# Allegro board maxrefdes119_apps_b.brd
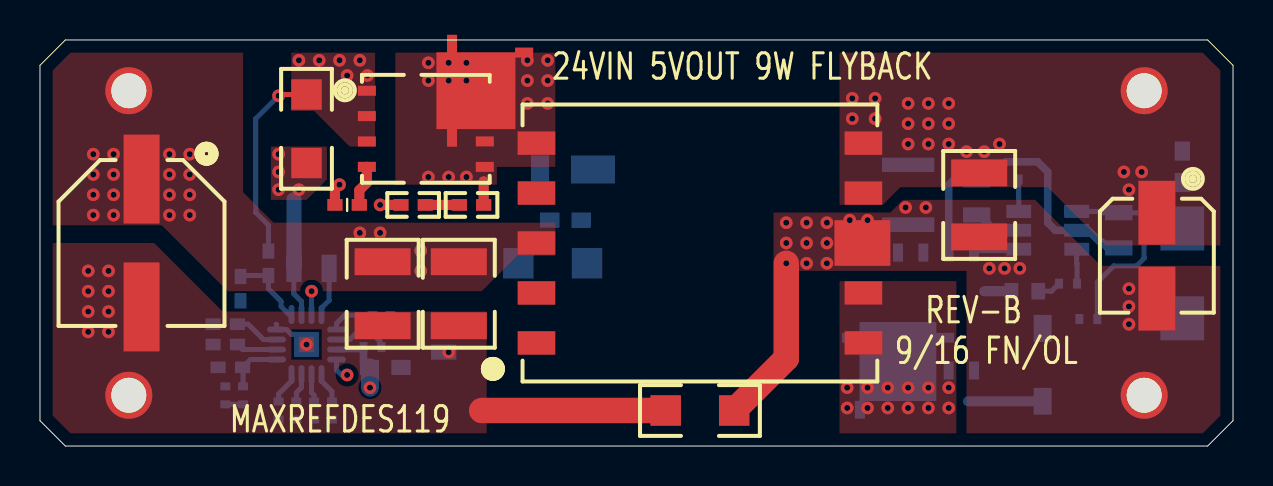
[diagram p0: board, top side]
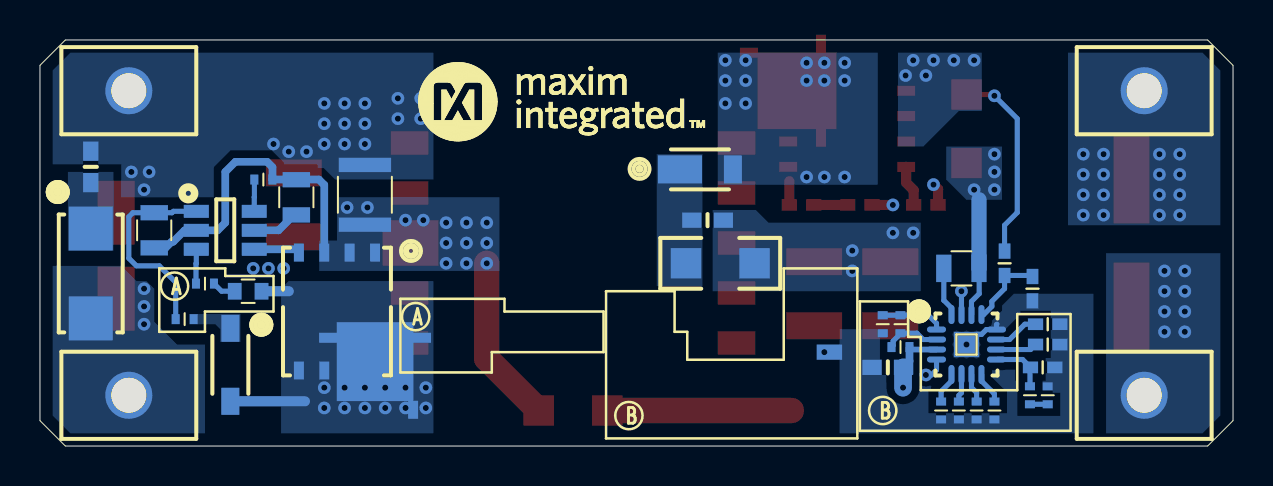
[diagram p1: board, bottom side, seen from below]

Outline 59.69 x 20.32 mm; copper layers: TOP, LAYER2, LAYER3, BOTTOM. Coordinates in mm from the lower left corner of the outline.
Outline path: 0,19.05 1.27,20.32 58.42,20.32 59.69,19.05 59.69,1.27 58.42,0 1.27,0 0,1.27 0,19.05

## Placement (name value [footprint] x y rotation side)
C1  47UF  [CAPAE830X690M]  5.08 10.16 270 top
C2  10UF  [1210]  20.95 7.62 270 top
C3  10UF  [1210]  17.14 7.62 270 top
C6  1UF  [0603#2]  17.27 3.94 0 bottom
C7  2.2UF  [CAPC2012X140M]  13.59 8.89 0 bottom
C8  22000PF  [0603#2]  26.29 11.3 0 bottom
C9  4700PF  [0402]  9.27 5.08 180 bottom
C10  0.033UF  [0402#2]  9.27 2.54 90 bottom
C12  330PF  [0402]  9.53 3.94 180 bottom
C14  1000PF  [1206]  33.02 1.78 0 top
C15  2.2UF  [CAPC2012X140M]  53.98 10.79 270 bottom
C16  2.2UF  [CAPC2012X140M]  46.86 12.45 90 bottom
C17  100UF  [1210]  46.99 12.06 270 top
C18  220UF  [CAPAE530X600M]  55.88 9.53 270 top
C19  OPEN  [0402]  10.03 7.87 270 bottom
C20  OPEN  [1210#2]  43.43 12.57 270 bottom
D1  DFLS2100  [POWERI123]  26.67 13.84 180 bottom
D2  1N4148W-7-F  [SOD3718X135M]  50.16 4.06 270 bottom
D3  5.6V  [DIOM5528X230M]  57.15 8.64 270 bottom
EV_KIT_BOX1  SMALL BOX  [EVKIT_PACKAGING]  91.82 82.42 0 top
GNDO  FWJ-01-01-T-S  [SAMTEC_FWJ-01-01-X-X]  55.24 2.54 90 bottom
NOREF  -  []  0 19.05 0 top
NOREF#2  -  []  31.75 52.7 0 top
NOREF#3  -  []  55.24 2.54 90 top
NOREF#4  -  []  4.45 17.78 0 top
NOREF#5  -  []  59 0.58 0 top
NOREF#6  -  []  1.27 0 90 top
NOREF#7  -  []  12.7 -8.26 0 top
NOREF#8  -  []  38.73 17.14 180 bottom
PGND  FWJ-01-01-T-S  [SAMTEC_FWJ-01-01-X-X]  4.45 2.54 90 bottom
PTC1  470  [0603]  49.28 7.75 0 bottom
Q1  FDMS86200DC  [SON127P615X500X112-8M_POWERPAK_SINGLE]  19.3 15.88 0 top
Q2  SIR426DP-T1-GE3  [SON127P615X500X112-8M_POWERPAK_SINGLE]  44.83 6.73 270 bottom
R1  10K  [0402#2]  17.53 6.1 90 bottom
R2  280K  [0402#2]  16.64 4.95 180 bottom
R3  11.8K  [0402#2]  16.64 6.1 270 bottom
R4  0  [0402]  21.59 12.06 180 top
R5  232K  [0402]  18.67 12.06 180 top
R6  10K  [0402#2]  14.61 1.78 270 bottom
R7  OPEN  [0402#2]  13.72 1.78 270 bottom
R8  75K  [0402#2]  12.83 1.78 270 bottom
R9  11.5K  [1206]  25.65 9.14 0 bottom
R10  140K  [0402#2]  11.94 1.78 270 bottom
R11  54.9K  [0402]  9.27 6.1 180 bottom
R12  9.09K  [0402#2]  10.16 2.54 270 bottom
R13  2.2  [0402]  15.37 12.06 0 top
R16  0.03  [1206]  13.34 15.88 270 top
R17  10  [0402#2]  52.45 6.35 180 bottom
R18  2.43K  [0402#2]  51.44 8.13 180 bottom
R19  100K  [0402#2]  48.51 13.34 180 bottom
R21  49.9  [0603#2]  57.15 13.97 270 bottom
R23  0  [0402]  11.43 9.14 90 bottom
T1  750316204  [XFMR_750316204]  33.02 10.16 0 top
U1  MAX17690ATE+  [QFN50P300X300X80-17M]  13.34 5.08 180 bottom
U2  MAX17606AZT+  [SOT95P280X110-6M]  50.42 10.79 180 bottom
VIN  FWJ-01-01-T-S  [SAMTEC_FWJ-01-01-X-X]  4.45 17.78 90 bottom
VOUT  FWJ-01-01-T-S  [SAMTEC_FWJ-01-01-X-X]  55.24 17.78 90 bottom
W1  -  [EVKIT_WIRE]  7.62 22.23 0 top

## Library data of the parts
C1 = CAP_POL: part number: CAP_POL_CASEE-CAPAE830X690M,47UF,20-0047U-A49
C2 C3 = CAP_NP: alternate symbols: CAPC3225X270L; part number: CAP_NP_1210CAP-1210,10UF,20-0010U-B40
C6 = CAP_NP: alternate symbols: (0603_NOSILK); part number: CAP_NP_0603CAP-0603,1UF,20-0001U-14
C7 C15 C16 = CAP_NP: alternate symbols: CAPC2012X145L; part number: CAP_NP_0805CAP-CAPC2012X140M,2.2UF,20-002U2-CA42
C8 = CAP_NP: alternate symbols: 0603_NOSILK,CAPC1608X90L; part number: CAP_NP_0603CAP-0603,22000PF,20-0U022-08
C9 = CAP_NP: alternate symbols: 0402_NOSILK,CAPC1005X50L; part number: CAP_NP_0402CAP-0402,4700PF,20-4700P-14
C10 = CAP_NP: alternate symbols: 0402_NOSILK,CAPC1005X50L; part number: CAP_NP_0402CAP-0402,0.033UF,20-0U033-04C
C12 = CAP_NP: alternate symbols: 0402_NOSILK,CAPC1005X50L; part number: CAP_NP_0402CAP-0402,330PF,20-0330P-F3
C14 = CAP_NP: part number: CAP_NP_1206CAP-1206,1000PF,20-1000P-08B
C17 = CAP_NP: alternate symbols: CAPC3225X270L; part number: CAP_NP_1210CAP-1210,100UF,20-0100U-CA19
C18 = CAP_POL: part number: CAP_POL_CASE_B6-CAPAE530X600M,220UF,20-0220U-CA36
C19 = EVK_GENERIC_CAPACITORS: alternate symbols: 0402_NOSILK,CAPC1005X50L; part number: EVK_GENERIC_CAPACITORS_0402CAP-0402,N/A
C20 = EVK_GENERIC_CAPACITORS: alternate symbols: CAPC3225X270L; part number: EVK_GENERIC_CAPACITORS_1210CAP-1210,N/A
D1 = DIO_SCHOTTKY: alternate symbols: SODFL3717X100L; part number: DIO_SCHOTTKY_POWERI123-POWERI123,DFLS2100,30-DFLS2100-00
D2 = DIO_SWITCH: part number: DIO_SWITCH_SOD-123-SOD3718X135M,1N4148W-7-F,30-1N4148W7F-00
D3 = DIO_ZENER: part number: DIO_ZENER_DO-214AC-DIOM5528X230M,5.6V,30-SMAZ5V6-00
EV_KIT_BOX1 = EV_KIT_BOX: part number: EV_KIT_BOX_ACCESSORY-N/A,SMALL BOX,EVKIT_PACKAGING
GNDO PGND VIN VOUT = HEADER_1P: part number: HEADER_1P_TH-SAMTEC_FWJ-01-01-X-X,FWJ-01-01-T-S,01-FWJ0101TS1P-19
PTC1 = THERMISTOR_SMD: alternate symbols: RESC1608X90L; part number: THERMISTOR_SMD_0603-0603,470,83-0470R-0AD
Q1 = TRAN_NCH_8P: alternate symbols: SON127P615X500X112-8L_POWERPAK_SINGLE; part number: TRAN_NCH_8P_POWERPAK-SINGLE-SON127P615X500X112-8M_POWERPAK_SINGLE,FDMS86200DC,90-FDMS86200DC-23
Q2 = TRAN_NCH_8P: part number: TRAN_NCH_8P_POWERPAK-SINGLE-SON127P615X500X112-8M_POWERPAK_SINGLE,SIR426DP-T1-GE3,90-SIR426DPT1GE3-23
R1 R6 = RES: alternate symbols: 0402_NOSILK,RESC1005X50L; part number: RES_0402RES-0402,10K,80-0010K-23E
R2 = RES: alternate symbols: 0402_NOSILK,RESC1005X50L; part number: RES_0402RES-0402,280K,80-0280K-BA37
R3 = RES: alternate symbols: 0402_NOSILK,RESC1005X50L; part number: RES_0402RES-0402,11.8K,80-011K8-AA23
R4 R23 = RES: alternate symbols: 0402_NOSILK,RESC1005X50L; part number: RES_0402RES-0402,0,80-0000R-BA38
R5 = RES: alternate symbols: 0402_NOSILK,RESC1005X50L; part number: RES_0402RES-0402,232K,80-0232K-BA37
R7 = EVK_GENERIC_RESISTORS: alternate symbols: 0402_NOSILK,RESC1005X50L; part number: EVK_GENERIC_RESISTORS_0402RES-0402,N/A
R8 = RES: alternate symbols: 0402_NOSILK,RESC1005X50L; part number: RES_0402RES-0402,75K,80-0075K-BA29
R9 = RES: part number: RES_1206RES-1206,11.5K,80-011K5-69
R10 = RES: alternate symbols: (0402_NOSILK,RESC1005X50L); part number: RES_0402RES-0402,140K,80-0140K-18
R11 = RES: alternate symbols: 0402_NOSILK,RESC1005X50L; part number: RES_0402RES-0402,54.9K,80-054K9-BA37
R12 = RES: alternate symbols: 0402_NOSILK,RESC1005X50L; part number: RES_0402RES-0402,9.09K,80-09K09-AA23
R13 = RES: alternate symbols: 0402_NOSILK,RESC1005X50L; part number: RES_0402RES-0402,2.2,80-002R2-BA36
R16 = RES: alternate symbols: RESC3116X60L; part number: RES_1206RES-1206,0.03,80-00R03-BA25
R17 = RES: alternate symbols: 0402_NOSILK,RESC1005X50L; part number: RES_0402RES-0402,10,80-0010R-BA36
R18 = RES: alternate symbols: (0402_NOSILK,RESC1005X50L); part number: RES_0402RES-0402,2.43K,80-02K43-18
R19 = RES: alternate symbols: 0402_NOSILK,RESC1005X50L; part number: RES_0402RES-0402,100K,80-0100K-BA37
R21 = RES: alternate symbols: 0603_NOSILK,RESC1608X90L; part number: RES_0603RES-0603,49.9,80-049R9-BA59
T1 = 750316204: part number: 750316204_SMD10-XFMR_750316204,750316204,12-750316204-01
U1 = MAX17690: part number: MAX17690_TQFN16-EP-QFN50P300X300X80-17M,MAX17690ATE+,10-MAX17690ATE-T
U2 = MAX17606: part number: MAX17606_SOT23-6-SOT95P280X110-6M,MAX17606AZT+,10-MAX17606AZT-Z
W1 = EVKIT_WIRE: part number: EVKIT_WIRE_WIRE-EVKIT_WIRE,N/A,EVKIT_WIRE

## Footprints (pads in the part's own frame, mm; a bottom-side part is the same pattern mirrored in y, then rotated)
0402
  rect 0.762x0.584 smd: 1(-0.61,0) 2(0.61,0)
0402#2
  rect 0.4x0.5 smd: 1(-0.45,0) 2(0.45,0)
0603
  rect 0.69x0.83 smd: 1(-0.67,0) 2(0.67,0)
0603#2
  rect 0.965x0.762 smd: 1(-0.787,0) 2(0.787,0)
1206
  rect 1.524x1.524 smd: 1(-1.714,0) 2(1.714,0)
1210
  rect 1.35x2.8 smd: 1(-1.6,0) 2(1.6,0)
1210#2
  rect 0.72x2.62 smd: 1(-1.495,0) 2(1.495,0)
CAPAE530X600M
  rect 3.2x1.85 smd: A(-2.15,0) K(2.15,0)
CAPAE830X690M
  rect 4.45x1.8 smd: 1(-3.2,0) 2(3.2,0)
CAPC2012X140M
  rect 0.76x1.37 smd: 1(-0.88,0) 2(0.88,0)
DIOM5528X230M
  rect 2.2x2.2 smd: A(2.25,0) C(-2.25,0)
POWERI123
  rect 0.9x1.4 smd: A(1.65,0)
  rect 2.2x1.4 smd: C(-0.999,0)
QFN50P300X300X80-17M
  oval 0.95x0.3 smd: 1(-1.5,0.75) 2(-1.5,0.25) 3(-1.5,-0.25) 4(-1.5,-0.75) 9(1.5,-0.75) 10(1.5,-0.25) 11(1.5,0.25) 12(1.5,0.75)
  oval 0.3x0.95 smd: 5(-0.75,-1.5) 6(-0.25,-1.5) 7(0.25,-1.5) 8(0.75,-1.5) 13(0.75,1.5) 14(0.25,1.5) 15(-0.25,1.5) 16(-0.75,1.5)
  rect 1.25x1.25 smd: 17(0,0)
SAMTEC_FWJ-01-01-X-X
  round 2.35 hole 1.75: 1(0,0)
SOD3718X135M
  rect 1.35x0.9 smd: A(1.825,0) C(-1.825,0)
SON127P615X500X112-8M_POWERPAK_SINGLE
  rect 0.9x0.5 smd: 1(-2.95,1.905) 2(-2.95,0.635) 3(-2.95,-0.635) 4(-2.95,-1.905) 5(2.95,-1.905) 6(2.95,-0.635) 7(2.95,0.635)
  custom 1.209x1.209 smd: 8(2.95,1.905)
SOT95P280X110-6M
  rect 1.25x0.65 smd: 1(-1.45,0.95) 2(-1.45,0) 3(-1.45,-0.95) 4(1.45,-0.95) 5(1.45,0) 6(1.45,0.95)
XFMR_750316204
  rect 1.88x1.17 smd: 1(-8.18,-5) 2(-8.18,-2.5) 3(-8.18,0) 4(-8.18,2.5) 5(-8.18,5) 6(8.18,5) 7(8.18,2.5) 8(8.18,0) 9(8.18,-2.5) 10(8.18,-5)

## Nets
GNDO: C14.2 C15.2 C16.2 C17.2 C18.K(B) C20.2 D3.A GNDO.1 Q2.1(S1) Q2.2(S2) Q2.3(S3) R19.2 U2.2(GND)
PGND: C1.2(B) C2.2 C3.2 C7.1 C14.1 PGND.1 R16.2 U1.14(PGND)
SGND: C6.2 C9.2 C10.2 C12.2 C19.2 R1.1 R6.2 R7.2 R8.2 R10.2 R11.2 U1.12(SGND) U1.17(EP)
VIN: C1.1(A) C2.1 C3.1 C6.1 C8.1 R2.2 R9.1 T1.3 U1.3(VIN) VIN.1
LX: D1.A Q1.5(D1) Q1.6(D2) Q1.7(D3) Q1.8(D4) R4.1 T1.5
UNNAMED_4_CAPNP_I112_2: C8.2 D1.C(K) R9.2
UNNAMED_4_CAPNP_I179_2: C7.2 U1.16(INTVCC)
UNNAMED_4_CAPNP_I180_1: C16.1 U2.5(VDRV)
UNNAMED_4_CAPNP_I182_1: C12.1 R12.1 U1.9(COMP)
UNNAMED_4_CAPNP_I183_1: C10.1 R12.2
UNNAMED_4_CAPNP_I184_1: C15.1 R17.1 U2.1(VIN)
UNNAMED_4_CAPNP_I219_1: C9.1 U1.10(SS)
UNNAMED_4_DIOSWITCH_I187_A: D2.A PTC1.1 Q2.5(D1) Q2.6(D2) Q2.7(D3) Q2.8(D4) T1.9 T1.10
UNNAMED_4_DIOSWITCH_I187_K: D2.C(K) R17.2
UNNAMED_4_DIOZENER_I178_K: D3.C(K) R21.2
UNNAMED_4_EVKGENERICRESISTORS_I167_1: R7.1 U1.6(TC)
UNNAMED_4_MAX17606_I176_DRN: R18.1 U2.3(DRN)
UNNAMED_4_MAX17606_I176_GATE: Q2.4(G) U2.4(GATE)
UNNAMED_4_MAX17606_I176_TOFF: R19.1 U2.6(TOFF)
UNNAMED_4_MAX17690_I155_CS: C19.1 R23.1 U1.13(CS)
UNNAMED_4_MAX17690_I155_EN: R2.1 R3.2 U1.2(EN/UVLO)
UNNAMED_4_MAX17690_I155_FB: R5.2 U1.4(FB)
UNNAMED_4_MAX17690_I155_NDRV: R13.1 U1.15(NDRV)
UNNAMED_4_MAX17690_I155_OVI: R1.2 R3.1 U1.1(OVI)
UNNAMED_4_MAX17690_I155_RIN: R10.1 U1.8(RIN)
UNNAMED_4_MAX17690_I155_RT: R11.1 U1.11(RT)
UNNAMED_4_MAX17690_I155_SET: R6.1 U1.5(SET)
UNNAMED_4_MAX17690_I155_VCM: R8.1 U1.7(VCM)
UNNAMED_4_RESSMD_I169_1: Q1.1(S1) Q1.2(S2) Q1.3(S3) R16.1 R23.2
UNNAMED_4_RESSMD_I171_1: R4.2 R5.1
UNNAMED_4_RESSMD_I173_2: PTC1.2 R18.2
UNNAMED_4_RESSMD_I175_2: Q1.4(G) R13.2
VOUT: C17.1 C18.A C20.1 R21.1 T1.6 T1.7 VOUT.1

Pads without a net: T1 1 2 4 8

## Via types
v1: diameter 0.635, hole 0.305, TOP to BOTTOM, 111 vias

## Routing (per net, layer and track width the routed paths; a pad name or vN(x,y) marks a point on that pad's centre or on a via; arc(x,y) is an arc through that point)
GNDO: length 24.2
  TOP w1.27: C14.2 37.34,4.38 v1(37.34,9.14)
  BOTTOM w0.381: 45.47,9.94 45.47,13.07 45.74,13.34 46.85,13.34 C16.2 46.87,13.34 R19.2 48.06,13.34 48.06,13.95 48.33,14.22 49.91,14.22 50.42,13.72 50.42,11.18 50.8,10.79 U2.2 52.45,10.79 53.02,10.23 53.1,10.23 53.41,9.91 C15.2
  vias: v1(37.34,11.18) v1(37.34,10.16) v1(38.35,11.18) v1(38.35,10.16) v1(38.35,9.14) v1(39.37,11.18) v1(39.37,10.16) v1(39.37,9.14) v1(40.51,11.3) v1(41.4,11.3) v1(43.31,11.94) v1(44.32,11.94) v1(47.5,8.89) v1(48.26,8.89) v1(49.02,8.89) v1(54.48,7.87) v1(54.48,6.99) v1(54.48,6.1)
PGND: length 15.3
  TOP w0.381: 22.1,1.78 21.97,1.65
  TOP w1.27: C14.1 22.1,1.78
  BOTTOM w0.254: C7.1 12.7,8.88 12.7,7.62 13.08,7.24 U1.14
  BOTTOM w0.762: C7.1 12.71,12.32
  vias: v1(2.41,8.76) v1(2.41,7.75) v1(2.41,6.73) v1(2.41,5.71) v1(3.43,8.76) v1(3.43,7.75) v1(3.43,6.73) v1(3.43,5.71) v1(11.94,14.61) v1(11.94,13.72) v1(11.94,12.83) v1(12.95,12.83) v1(20.45,4.7)
SGND: length 2.2
  BOTTOM w0.254: 13.21,5.08 v1(13.34,5.08) 12.83,5.59 12.58,5.59 12.34,5.83 U1.12 11.84,6.07 11.81,6.1
VIN: length 10.5
  LAYER3 w0.762: v1(19.05,8.76) 16.51,6.22 v1(16.51,2.92)
  BOTTOM w0.279: U1.3 16.06,4.83 R2.2
  BOTTOM w0.381: C6.1 16.19,4.23 R2.2
  BOTTOM w0.889: C6.1 16.51,3.91 v1(16.51,2.92)
  vias: v1(2.67,14.61) v1(2.67,13.59) v1(2.67,12.57) v1(2.67,11.56) v1(3.68,14.61) v1(3.68,13.59) v1(3.68,12.57) v1(3.68,11.56) v1(6.48,14.61) v1(6.48,13.59) v1(6.48,12.57) v1(6.48,11.56) v1(7.49,14.61) v1(7.49,13.59) v1(7.49,12.57) v1(7.49,11.56) v1(16,10.67) v1(17.02,10.67) v1(19.05,9.78)
LX: length 1.2
  TOP w0.508: R4.1 22.2,13.25
  vias: v1(19.43,19.18) v1(19.43,18.29) v1(19.43,13.46) v1(20.45,19.18) v1(20.45,18.29) v1(20.45,13.46) v1(21.34,19.18) v1(21.34,18.29) v1(21.34,13.46) v1(24.38,19.3) v1(24.38,18.29) v1(24.38,17.14) v1(25.4,19.3) v1(25.4,18.29) v1(25.4,17.14)
UNNAMED_4_CAPNP_I179_2: length 2.5
  BOTTOM w0.254: U1.16 14.09,6.9 14.47,7.29 C7.2
UNNAMED_4_CAPNP_I180_1: length 2.4
  BOTTOM w0.381: U2.5 47.75,10.79 46.98,11.57 C16.1
UNNAMED_4_CAPNP_I182_1: length 2.8
  BOTTOM w0.254: R12.1 10.16,3.91 C12.1 10.53,4.33 U1.9
UNNAMED_4_CAPNP_I183_1: length 0.9
  BOTTOM w0.254: R12.2 C10.1
UNNAMED_4_CAPNP_I184_1: length 10.3
  BOTTOM w0.254: R17.1 52.9,8.2 53.72,9.02 54.86,9.02 55.24,9.4 55.24,11.47 55.04,11.68 C15.1 53.09,11.68 53.02,11.75 U2.1
UNNAMED_4_CAPNP_I219_1: length 2.1
  BOTTOM w0.254: C9.1 10.13,4.83 U1.10
UNNAMED_4_DIOSWITCH_I187_A: length 5.1
  BOTTOM w0.508: D2.A 46.44,2.24 ; PTC1.1 47.24,7.75
  vias: v1(40.39,2.92) v1(40.39,1.91) v1(41.4,2.92) v1(41.4,1.91) v1(42.42,2.92) v1(42.42,1.91) v1(43.43,2.92) v1(43.43,1.91) v1(44.45,2.92) v1(44.45,1.91) v1(45.47,2.92) v1(45.47,1.91)
UNNAMED_4_EVKGENERICRESISTORS_I167_1: length 1.4
  BOTTOM w0.254: R7.1 13.72,2.54 13.59,2.67 U1.6
UNNAMED_4_MAX17606_I176_DRN: length 1.7
  BOTTOM w0.254: R18.1 51.89,9.12 51.87,9.14 U2.3
UNNAMED_4_MAX17606_I176_GATE: length 2.3
  BOTTOM w0.381: U2.4 46.9,9.84 Q2.4
UNNAMED_4_MAX17606_I176_TOFF: length 1.6
  BOTTOM w0.254: R19.1 48.96,12.46 48.97,12.45 U2.6
UNNAMED_4_MAX17690_I155_CS: length 3.9
  BOTTOM w0.254: U1.13 12.47,6.58 12.06,6.99 12.06,7.24 11.43,7.87 R23.1 10.08,8.53 C19.1
UNNAMED_4_MAX17690_I155_EN: length 2.8
  BOTTOM w0.254: R2.1 17,5.04 17,5.26 16.64,5.62 R3.2 15.82,5.65 15.5,5.33 U1.2
UNNAMED_4_MAX17690_I155_FB: length 12.5
  TOP w0.508: R5.2 v1(17.02,12.06)
  LAYER3 w0.508: v1(17.02,12.06) 15.75,12.06 14.99,11.3 14.99,7.24 15.37,6.86 v1(15.37,3.56)
  BOTTOM w0.254: v1(15.37,3.56) 15.09,3.56 14.83,3.81 U1.4
UNNAMED_4_MAX17690_I155_NDRV: length 8.2
  TOP w0.508: v1(14.99,13.08) 14.76,12.85 R13.1
  LAYER3 w0.508: v1(13.59,7.75) 13.59,11.68 v1(14.99,13.08)
  BOTTOM w0.254: U1.15 13.59,7.74 v1(13.59,7.75)
UNNAMED_4_MAX17690_I155_OVI: length 3.2
  BOTTOM w0.254: R1.2 R3.1 15.24,6.55 14.83,6.14 U1.1
UNNAMED_4_MAX17690_I155_RIN: length 1.6
  BOTTOM w0.254: R10.1 11.94,2.61 12.58,3.26 U1.8
UNNAMED_4_MAX17690_I155_RT: length 2.3
  BOTTOM w0.254: R11.1 10.41,6.1 11.18,5.33 U1.11
UNNAMED_4_MAX17690_I155_SET: length 1.6
  BOTTOM w0.254: R6.1 14.61,2.74 14.09,3.26 U1.5
UNNAMED_4_MAX17690_I155_VCM: length 1.5
  BOTTOM w0.254: R8.1 12.83,2.67 13.08,2.93 U1.7
UNNAMED_4_RESSMD_I169_1: length 9.9
  TOP w0.254: R16.1 12,17.59 v1(11.94,17.53)
  BOTTOM w0.254: R23.2 11.43,11.05 10.79,11.68 10.79,16.38 v1(11.94,17.53)
  vias: v1(12.95,19.3) v1(13.97,19.3) v1(14.99,19.3) v1(15.37,18.54) v1(16,19.3) v1(16.38,18.54)
UNNAMED_4_RESSMD_I171_1: length 1.7
  TOP w0.508: R4.2 R5.1
UNNAMED_4_RESSMD_I173_2: length 1.2
  BOTTOM w0.254: R18.2 50.6,7.75 PTC1.2
UNNAMED_4_RESSMD_I175_2: length 2.1
  TOP w0.508: R13.2 15.98,12.8 16.35,13.18 Q1.4
VOUT:
  vias: v1(40.64,17.4) v1(40.64,16.38) v1(41.78,17.4) v1(41.78,16.38) v1(43.43,17.14) v1(43.43,16.13) v1(43.43,15.11) v1(44.45,17.14) v1(44.45,16.13) v1(44.45,15.11) v1(45.47,17.14) v1(45.47,16.13) v1(45.47,15.11) v1(46.35,14.73) v1(47.24,14.73) v1(48.01,15.11) v1(54.23,13.72) v1(54.48,12.83) v1(55.12,13.72)

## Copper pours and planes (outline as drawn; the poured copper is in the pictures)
GNDO on TOP (solid shape): 42.55,9.02 39.75,9.02 39.75,11.3 42.55,11.3
GNDO on TOP, LAYER2, LAYER3: 58.17,0.64 59.05,1.52 59.05,9.02 53.21,9.02 53.09,9.02 49.78,12.32 43.18,12.32 42.55,11.68 36.7,11.68 36.7,8.76 46.35,0.64
GNDO on BOTTOM: 45.72,10.29 44.83,10.29 44.83,12.45 36.7,12.45 36.7,8.76 45.72,8.76
GNDO on BOTTOM: 58.17,0.64 59.05,1.52 59.05,9.02 55.63,9.02 54.86,8.26 54.36,8.26 53.98,7.87 53.98,6.22 52.83,5.08 51.44,5.08 51.44,0.64
PGND on TOP: 22.35,0.64 22.35,6.73 9.14,6.73 5.71,10.16 0.64,10.16 0.64,1.52 1.52,0.64
PGND on TOP, BOTTOM: 14.35,14.99 14.35,13.34 13.34,12.32 11.56,12.32 11.56,14.99
PGND on BOTTOM: 0.64,1.52 1.52,0.64 6.35,0.64 6.35,9.65 0.64,9.65
PGND on LAYER2, LAYER3: 1.52,0.64 0.64,1.52 0.64,9.65 8.89,9.65 9.53,10.29 9.53,14.99 14.35,14.99 14.35,13.34 13.34,12.32 13.34,10.16 8.26,5.08 8.26,0.64
SGND on BOTTOM: 19.68,0.64 19.68,5.84 17.02,5.84 15.24,7.62 6.99,7.62 6.99,0.64
SGND on LAYER2: 19.68,0.64 19.68,5.84 17.02,5.84 16.38,5.84 14.61,7.62 6.99,7.62 6.99,7.62 6.99,0.64
SGND on LAYER3: 8.89,0.64 19.68,0.64 19.68,5.84 17.02,5.84 16.38,5.84 14.61,7.62 11.68,7.62 8.89,4.83
VIN on TOP: 6.1,11.05 0.64,11.05 0.64,18.8 1.52,19.68 10.16,19.68 10.16,12.7 11.68,11.18 25.78,11.18 25.78,9.53 23.88,9.53 22.1,7.75 9.4,7.75
VIN on BOTTOM: 15.62,7.75 15.62,11.18 23.24,11.18 23.88,11.81 26.04,11.81 26.04,7.75
VIN on BOTTOM, LAYER2: 0.64,11.05 0.64,18.8 1.52,19.68 8.26,19.68 8.26,11.05
VIN on LAYER3: 0.64,11.05 0.64,18.8 1.52,19.68 8.26,19.68 8.26,11.05
LX on TOP, LAYER2, LAYER3: 17.78,19.68 17.78,13.08 22.86,13.08 22.86,13.97 25.78,13.97 25.78,19.68
LX on BOTTOM: 17.78,19.68 17.78,13.08 25.78,13.08 25.78,19.68
UNNAMED_4_CAPNP_I112_2 on BOTTOM: 26.54,14.61 28.83,14.61 28.83,8 26.54,8
UNNAMED_4_DIOSWITCH_I187_A on TOP, LAYER2, LAYER3: 40.01,8.26 45.85,8.26 45.85,0.64 40.01,0.64
UNNAMED_4_DIOSWITCH_I187_A on BOTTOM: 40.01,8.26 40.01,8.25 47.24,8.25 47.62,7.87 47.62,0.64 40.01,0.64
UNNAMED_4_DIOSWITCH_I187_K on BOTTOM: 52.2,6.6 52.2,6.1 50.93,6.1 50.67,5.84 50.67,5.21 49.66,5.21 49.66,6.6
UNNAMED_4_DIOZENER_I178_K on BOTTOM: 56.01,9.78 58.29,9.78 58.29,13.72 56.01,13.72
UNNAMED_4_RESSMD_I169_1 on TOP, BOTTOM, LAYER2, LAYER3: 12.57,16.76 13.72,16.76 15.49,14.99 16.76,14.99 16.76,19.68 12.57,19.68
VOUT on TOP, LAYER2, LAYER3: 59.05,18.8 58.17,19.68 40.01,19.68 40.01,12.06 42.16,12.06 43.05,12.95 50.42,12.95 53.34,10.03 59.05,10.03
VOUT on BOTTOM: 58.17,19.68 59.05,18.8 59.05,14.1 55.63,14.1 55.63,12.45 50.8,12.45 50.8,13.34 40.01,13.34 40.01,19.68

Small or netless copper shapes (teardrops, artwork), in the pictures only: 1 on BOTTOM, 1 on TOP

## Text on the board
Ref Des/Silkscreen Bottom: B | A
Ref Des/Silkscreen Top: MAXREFDES119 | 24VIN 5VOUT 9W FLYBACK | 9/16 FN/OL | REV-B
DIMENSION: NOTES: | FINISH: | TESTING: | MISCELLANEOUS: | TOOLING: | 16.  VENDOR LOGO & DATE CODE REQUIRED IN INK ON BOTTOM SIDE ONLY. DATE CODE FORMAT MUST BE YYWW ONLY | 17.  FINAL ELECTRICAL TEST TO BE PERFORMED USING PROVIDED IPC-D-356A NETLIST OR ODB++ FORMAT FILE. | 18.  A TIME DOMAIN REFLECTOMETER REPORT FOR EACH IMPEDANCE CONTROLLED LAYER AND A CERTIFICATE | 15.  CHECK ALL THAT APPLY | 14.  CHECK ALL THAT APPLY | 19. IF PRESENT, ALL BLIND/BURIED VIAS WITH AN ASPECT RATIO <1:1 TO BE PLATED SHUT WITH COPPER WHEN | 20.  FOR ALL DRILL INFORMATION REFER TO DRILL CHART. | 21.  FINISHED SURFACE CONTACTS AND FILLED VIAS TO BE FREE OF ANY PITS. SCRATCHES PROBE MARKS | 23.  PEMNUT | 13.  DRILL SIZES ARE FINISHED HOLE SIZES. ALL HOLES SHALL BE LOCATED WITHIN .005 DTP. | 22.  THIEVING: | 9.  ALL TRACES FILLETED OPTION TO ENHANCE RELIABILITY AT PAD JUNCTIONS | 10.  LAYER TO LAYER REGISTRATIONS SHALL BE WITHIN .003 INCHES. | MATERIAL: | 11.  PLATING SPECIFICATION: | 12.  CHECK ALL THAT APPLY | 8.  IF STATED IN THE LAMINATION DIAGRAM, THE DIELECTRIC THICKNESS OF ANY | 1.  DIMENSIONS ARE IN INCHES (EXCEPT WHERE NOTED). | 3.  THE PCB SHALL BE FABRICATED TO IPC-6012, TYPE X, CLASS 2. | 4.  BOARD MATERIAL & CONSTRUCTION SHALL MEET THE REQUIREMENTS OF UL796 | 5.  OVERALL BOARD THICKNESS REFER TO LAMINATION DIAGRAM. TOLERANCE APPLIES | 6.  BOW & TWIST NOT TO EXCEED 0.0075 IN. (0.75%) PER LINEAR INCH. | 7.  PHOTO ETCH CIRCUITRY PER ENCLOSED GERBER RS274X OR ODB++ FORMAT FILE. | 2.  BOARD MATERIAL: | ( )  FINISH CONDUCTOR SURFACES: IMMERSION GOLD, 2-5 MICRO INCHES OVER | (X)  STARTING COPPER WEIGHT FOR OUTER LAYERS TO BE (1 OZ), THE FINISH COPPER WEIGHT IS (1 OZ). | ( )  STARTING COPPER WEIGHT FOR OUTER LAYERS TO BE (1 OZ), THE FINISH COPPER WEIGHT IS (2 OZ). | ( )  STARTING COPPER WEIGHT FOR OUTER LAYERS TO BE (2 OZ), THE FINISH COPPER WEIGHT IS (2 OZ)MINIMUM. | ( )  OTHER ________________________ | ( )  FINISH CONDUCTOR SURFACES: IMMERSION GOLD, 3-8 MICRO INCHES OVER | ( )  FINGERS TO BE GOLD PLATED. | (X)  LEAD FREE AND RoHS COMPLIANT PLATING. | (X)  GREEN SOLDERMASK OVER BARE COPPER/BARE GOLD (BOTH SIDES) WITH LIQUID PHOTO IMAGEABLE INK (LPI) | ( )  GREEN TAIYO PSR-4000 | ( )  ELECTRODEPOSITED HARD GOLD PLATE, TYPE 1 (99.7% MIN GOLD), GRADE C | (X)  APPLY SILKSCREEN USING A NON-CONDUCTIVE, WHITE EPOXY | THE STARTING WEIGHT CAN BE (0.5 OZ) AS LONG AS THE FINISH COPPER WEIGHT IS (2 OZ). | THE STARTING WEIGHT CAN BE (<2 OZ) AS LONG AS THE FINISH COPPER WEIGHT IS (2 OZ). | MINIMUM BARREL PLATING OF .001 IN. PLATED HOLES SHALL NOT BE ROUGH OR IRREGULAR | SO AS TO HINDER PROPER SOLDER WICKING. | USED AS VIA-IN PAD OR AS A STACKED VIA. BLIND/BURIED VIAS WITH AN ASPECT RATIO >1:1 TO BE FILLED | WITH NON-CONDUCTIVE EPOXY. UNLESS OTHERWISE SPECIFIED. | ( )  NON-CONDUCTIVE EPOXY. FILL AND CAP ALL 0.XXXX INCH DRILLED VIAS. | ( )  SILVER. FILL AND CAP ALL 0.XXXX INCH DRILLED VIAS. | (REQUIRED UNLESS OTHERWISE SPECIFIED IN QUOTE) | THE PCB SHALL HAVE A VERIFICATION STAMP. | OF COMPLIANCE SHALL BE PROVIDED BY VENDOR AT TIME OF SHIPMENT. | OR OTHER DEFORMITIES THAT COULD EFFECT THE APPERANCE AND PERFORMACE OF THE CONTACT | SURFACE. CONTACTS ARE TO BE AS FLAT AS POSSIBLE. NOT TO EXCEED +/- 0.001" OF FLATNESS. | ( )  SUPPLIER MAY ADD THIEVING TO COMPENSATE FOR LOW COPPER DENSITY AREAS ON THIS DESIGN. | WHERE SPACING PERMITS. | LEGEND TO LEGEND +/- 0.007 INCHES | (X)  SUPPLIER MAY NOT ADD THIEVING TO COMPENSATE FOR LOW COPPER DENSITY AREAS ON THIS DESIGN. | ( )  PEMNUTS TO BE INSTALLED BY SUPPLIER. | ( )  PEMNUTS NOT TO BE INSTALLED BY SUPPLIER. | (X)  NOT APPLICABLE | CONTROLLED IMPEDANCE LAYER IS FOR REFERENCE ONLY. FINAL ACCEPTANCE | SHALL BE DETERMINED BY THESE LAYERS HAVING A CHARACTERISTIC | IMPEDANCE OF +/-10% OHMS AS STATED IN THE LAMINATION DIAGRAM. THE | VENDOR CAN MAKE ADJUSTMENTS AS LONG AS THE STATED IMPEDANCE AND | OVERALL BOARD THICKNESS IS MAINTAINED. ANY ADJUSTMENT MADE TO TRACE | WIDTH OR SPACING MUST HAVE PRIOR WRITTEN APPROVAL FROM MAXIM. | ( )  FILLETED | (X)  NOT FILLETED | (X)  ISOLA 370HR OR EQUIVALENT | ( )  NELCO-4000-13 | ( )  MEGTRON 6 | ( )  ROGERS 4350B | ( )  ROGERS 4003C | ( )  ISOLA-FR408HR OR EQUIVALENT | WORKMANSHIP SHALL CONFORM TO IPC-A-600, CLASS 2, CURRENT REVISIONS. | WITH FLAMMABILITY RATING OF 94V-O. | AFTER ALL LAMINATION AND PLATING PROCESSES. IT IS TO BE MEASURED FROM | TOP PCB METAL TO BOTTOM PCB METAL UNLESS OTHERWISE SPECIFIED. | BOW & TWIST SHOULD BE MEASURED PER IPC-TM-650, METHOD 2.4.22. | DRILL LOCATION AND SIZE CONTROLLED BY EXCELLON CNC DRILL FILE. | FOR OUTER LAYERS WHERE SPACING PREVENTS THE USE OF (1 OZ) AS A STARTING WEIGHT, | FOR OUTER LAYERS WHERE SPACING PREVENTS THE USE OF (2 OZ) AS A STARTING WEIGHT, | UNLESS OTHERWISE SPECIFIED | FOR OUTER LAYERS WHERE SPACING PREVENTS THE USE OF (1 OZ) AS A STARTING WEIGHT | THE STARTING WEIGHT CAN BE (0.5 OZ) AS LONG AS THE FINISH COPPER WEIGHT IS (1 OZ) | (KNOOP HARDNESS 130-200), CLASS 1 (50-100 MICRO INCHES THICK) IN ACCORDANCE WITH MIL-G-45204C. | GENERAL SURFACING REQUIREMENTS MUST MEET ANSI/IPC-A-600(CURRENT REV) SECTION 4.0, | CLASS 3 (50-100 MICROINCHES THICK) OVER ELECTRODEPOSITED NICKEL PLATE | IN ACCORDANCE WITH ANSI/IPC-A-600D, SECTION 4.0, CLASS 3 (200-600 MICROINCHES THICK). | 100 MICRO INCHES MINIMUM OF ELECTROLESS NICKEL. | 118-236 MICRO INCHES MINIMUM OF ELECTROLESS NICKEL. | PER ARTWORK. | BASED INK PER ARTWORK. | (USE CHECKED ITEMS FOR MATERIAL) | (USE CHECKED ITEMS FOR PLATING) | (USE CHECKED ITEMS FOR TOOLING) | UNLESS OTHERWISE SPECIFIED: | TOLERANCES UNLESS OTHERWISE SPECIFIED | FRACTIONS | SEE NOTES | .XXX +/- .005 | .XX +/- .01 | DECIMALS | +/- | ANGLES | THE INFORMATION CONTAINED IN THIS DOCUMENT | IS PROPRIETARY TO MAXIM. THE INFORMATION IN | THIS DOCUMENT IS NOT TO BE SHOWN, REPRODUCED, | OR DISCLOSED TO ANYONE OUTSIDE OF MAXIM | WITHOUT PRIOR WRITTEN PERMISSION FROM MAXIM. | NOT TO SCALE | x4 corners | DRAWN BY: | CHECKED BY: | APPR. BY: | DATE: | 9/22/16 | HARDWARE NUMBER: | 24VIN 5VOUT 9W FLYBACK CONVERTER | TEMPLATE REV B | SHEET 1 OF 1 | REV | HARDWARE NAME: | MAXREFDES119 | B | DESCRIPTION | REVISIONS | APPROVED | DATE
User.16: FIGURE | SIZE | 12.0 | 68.898 | DRILL CHART: TOP to BOTTOM | ALL UNITS ARE IN MILS | TOLERANCE | +3.0/-10.0 | +3.0/-3.0 | PLATED | QTY | 111 | 4
User.22: 1"
